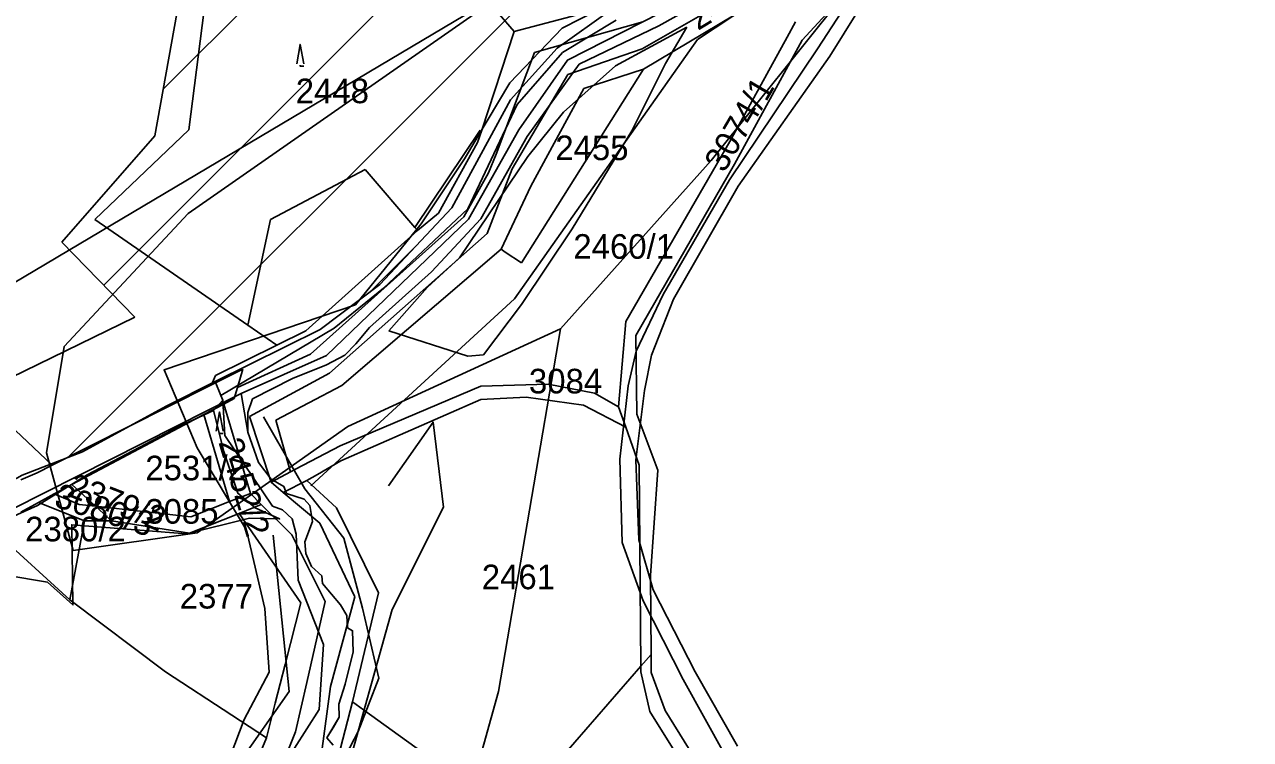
# Model space of a CAD drawing. Extents: x -564810 to -550519, y -1045831 to -1034011.
# Drawn here: x -551752.9 to -551498.8, y -1037775.2 to -1037627.1 of the extents above; entities that cross this region are included whole.
import ezdxf

# ---------------------------------------------------------------- set-up
doc = ezdxf.new("R2010")
doc.units = 0
for name, color, linetype in [('Interakční prvky', 7, 'Continuous'), ('KN stav', 7, 'Continuous'), ('Lesní porost', 7, 'Continuous'), ('Parcelní čísla', 7, 'Continuous'), ('Polní cesty stavající', 7, 'Continuous'), ('STG', 7, 'Continuous'), ('vodní toky', 7, 'Continuous'), ('Vrstva 18', 7, 'Continuous'), ('Vrstva 33', 7, 'Continuous'), ('Vrstva 4', 7, 'Continuous'), ('zamokř ploch', 7, 'Continuous')]:
    doc.layers.add(name, color=color, linetype=linetype)

msp = doc.modelspace()

# ---------------------------------------------------------------- linework, layer by layer
at = {"layer": 'Interakční prvky'}
msp.add_lwpolyline([(-551815.2, -1038103.87), (-551768.89, -1038062), (-551754.38, -1038041.34), (-551734.29, -1037993.33), (-551703.6, -1037883.91), (-551714.2, -1037828.76), (-551708.61, -1037780.35), (-551698.01, -1037765.28), (-551701.36, -1037732.9)], dxfattribs=at)
at = {"layer": 'KN stav'}
for p, q in [((-551667.33, -1037609.97), (-551651.38, -1037628.5)), ((-551624.88, -1037632.08), (-551586.71, -1037610.2)), ((-551574.97, -1037612.18), (-551591.71, -1037630.26)), ((-551718.79, -1037648.87), (-551714.95, -1037618.6)), ((-551651.38, -1037628.5), (-551628.05, -1037622.34)), ((-551602.54, -1037623.18), (-551624.56, -1037636.32)), ((-551624.72, -1037626.5), (-551647.19, -1037632.84)), ((-551594.84, -1037629.65), (-551593.1, -1037626.47)), ((-551651.38, -1037628.5), (-551658.1, -1037648.95)), ((-551606.67, -1037651.28), (-551594.84, -1037629.65)), ((-551591.71, -1037630.26), (-551605.76, -1037655.96)), ((-551647.19, -1037632.84), (-551655.15, -1037653.95)), ((-551640.25, -1037637.4), (-551624.88, -1037632.08)), ((-551624.56, -1037636.32), (-551649.88, -1037676.41)), ((-551636.95, -1037640.33), (-551624.56, -1037636.32)), ((-551651.83, -1037656.95), (-551640.25, -1037637.4)), ((-551647.92, -1037660.53), (-551636.95, -1037640.33)), ((-551738.32, -1037667.46), (-551718.79, -1037648.87)), ((-551658.1, -1037648.95), (-551658.97, -1037651.49)), ((-551658.97, -1037651.49), (-551667.1, -1037666.17)), ((-551628.22, -1037688.57), (-551606.67, -1037651.28)), ((-551655.15, -1037653.95), (-551656.73, -1037657.8)), ((-551656.99, -1037670.36), (-551651.83, -1037656.95)), ((-551605.76, -1037655.96), (-551626.14, -1037691.53)), ((-551656.73, -1037657.8), (-551661.85, -1037666.91)), ((-551654.09, -1037673.64), (-551647.92, -1037660.53)), ((-551706.6, -1037689.39), (-551738.32, -1037667.46)), ((-551661.85, -1037666.91), (-551693.62, -1037695.4)), ((-551667.1, -1037666.17), (-551671.45, -1037669.76)), ((-551671.45, -1037669.76), (-551694.55, -1037690.55)), ((-551689.67, -1037699.31), (-551656.99, -1037670.36)), ((-551654.09, -1037673.64), (-551687.08, -1037701.85)), ((-551653.24, -1037674.2), (-551654.09, -1037673.64)), ((-551649.88, -1037676.41), (-551653.24, -1037674.2)), ((-551700.6, -1037693.54), (-551706.6, -1037689.39)), ((-551629.77, -1037706.31), (-551628.22, -1037688.57)), ((-551694.55, -1037690.55), (-551700.6, -1037693.54)), ((-551626.14, -1037691.53), (-551626, -1037707.78)), ((-551713.26, -1037699.78), (-551700.6, -1037693.54)), ((-551693.62, -1037695.4), (-551708.72, -1037702.26)), ((-551768.83, -1037697.93), (-551747.1, -1037718.36)), ((-551707.63, -1037698.48), (-551714.09, -1037701.73)), ((-551714.09, -1037701.73), (-551713.26, -1037699.78)), ((-551708.72, -1037702.26), (-551707.63, -1037698.48)), ((-551706.26, -1037708.3), (-551689.67, -1037699.31)), ((-551714.09, -1037701.73), (-551723.13, -1037706.29)), ((-551708.72, -1037702.26), (-551709.39, -1037704.55)), ((-551687.08, -1037701.85), (-551700.76, -1037709.06)), ((-551658.32, -1037701.99), (-551687.43, -1037714.36)), ((-551644.32, -1037701.62), (-551658.32, -1037701.99)), ((-551634.72, -1037703.43), (-551644.32, -1037701.62)), ((-551715.71, -1037707.9), (-551711.57, -1037705.7)), ((-551709.39, -1037704.55), (-551711.57, -1037705.7)), ((-551711.57, -1037705.7), (-551706.06, -1037724.25)), ((-551658.3, -1037704.79), (-551687.32, -1037717.46)), ((-551648.87, -1037704.27), (-551658.3, -1037704.79)), ((-551636.99, -1037705.97), (-551648.87, -1037704.27)), ((-551629.77, -1037706.31), (-551634.72, -1037703.43)), ((-551723.13, -1037706.29), (-551747.1, -1037718.36)), ((-551722.09, -1037711.28), (-551715.71, -1037707.9)), ((-551715.71, -1037707.9), (-551710.35, -1037725.92)), ((-551628.28, -1037710.49), (-551636.99, -1037705.97)), ((-551628.28, -1037710.49), (-551629.77, -1037706.31)), ((-551626, -1037707.78), (-551621.64, -1037719.38)), ((-551701.75, -1037721.9), (-551706.26, -1037708.3)), ((-551700.76, -1037709.06), (-551697.74, -1037719.79)), ((-551625.46, -1037718.38), (-551628.28, -1037710.49)), ((-551743.06, -1037722.39), (-551722.09, -1037711.28)), ((-551687.43, -1037714.36), (-551696.7, -1037719.24)), ((-551747.1, -1037718.36), (-551750.23, -1037719.94)), ((-551687.32, -1037717.46), (-551692.16, -1037720.28)), ((-551625.17, -1037760.06), (-551625.46, -1037718.38)), ((-551750.23, -1037719.94), (-551753.63, -1037721.44)), ((-551697.74, -1037719.79), (-551701.75, -1037721.9)), ((-551697.74, -1037719.79), (-551696.7, -1037719.24)), ((-551692.16, -1037720.28), (-551694.37, -1037721.57)), ((-551621.64, -1037719.38), (-551623.16, -1037741.27)), ((-551746.69, -1037724.31), (-551743.06, -1037722.39)), ((-551743.06, -1037722.39), (-551738.16, -1037726.88)), ((-551699.28, -1037724.04), (-551701.75, -1037721.9)), ((-551694.37, -1037721.57), (-551699.28, -1037724.04)), ((-551694.37, -1037721.57), (-551688.23, -1037727.19)), ((-551749.94, -1037726.09), (-551746.69, -1037724.31)), ((-551746.69, -1037724.31), (-551741.52, -1037726.51)), ((-551710.35, -1037725.92), (-551718.4, -1037729.06)), ((-551706.06, -1037724.25), (-551710.35, -1037725.92)), ((-551706.06, -1037724.25), (-551703.8, -1037726.56)), ((-551691.63, -1037730.42), (-551699.28, -1037724.04)), ((-551753.62, -1037728.1), (-551749.94, -1037726.09)), ((-551749.94, -1037726.09), (-551740.44, -1037729.94)), ((-551741.52, -1037726.51), (-551738.16, -1037726.88)), ((-551738.16, -1037726.88), (-551734.84, -1037729.93)), ((-551718.4, -1037729.06), (-551738.16, -1037726.88)), ((-551708.41, -1037728.4), (-551718.69, -1037732.49)), ((-551703.8, -1037726.56), (-551708.41, -1037728.4)), ((-551708.41, -1037728.4), (-551695.58, -1037746.9)), ((-551703.8, -1037726.56), (-551697.49, -1037732.79)), ((-551688.23, -1037727.19), (-551679.48, -1037744.81)), ((-551740.44, -1037729.94), (-551743.48, -1037746.26)), ((-551734.84, -1037729.93), (-551740.44, -1037729.94)), ((-551718.69, -1037732.49), (-551734.84, -1037729.93)), ((-551684.39, -1037745.68), (-551691.63, -1037730.42)), ((-551743.48, -1037746.26), (-551759.69, -1037731.54)), ((-551697.49, -1037732.79), (-551690.58, -1037746.6)), ((-551623.16, -1037741.27), (-551623.02, -1037757.59)), ((-551743.48, -1037746.26), (-551723.63, -1037761.18)), ((-551689.42, -1037764.26), (-551684.39, -1037745.68)), ((-551679.48, -1037744.81), (-551684.89, -1037767.43)), ((-551695.58, -1037746.9), (-551698.85, -1037759.7)), ((-551690.58, -1037746.6), (-551694.37, -1037763.41)), ((-551623.02, -1037757.59), (-551625.17, -1037760.06)), ((-551623.02, -1037757.59), (-551622.99, -1037761.32)), ((-551723.63, -1037761.18), (-551709.88, -1037770.22)), ((-551698.85, -1037759.7), (-551700.89, -1037767.73)), ((-551625.17, -1037760.06), (-551652.1, -1037791.03)), ((-551625.17, -1037760.06), (-551625.16, -1037761.21)), ((-551625.16, -1037761.21), (-551623.28, -1037769.41)), ((-551622.99, -1037761.32), (-551620.07, -1037769.24)), ((-551694.37, -1037763.41), (-551696.68, -1037773.64)), ((-551691.33, -1037778.14), (-551689.42, -1037764.26)), ((-551700.89, -1037767.73), (-551702.73, -1037774.92)), ((-551684.89, -1037767.43), (-551689.26, -1037784.27)), ((-551682.63, -1037769.06), (-551684.89, -1037767.43)), ((-551652.1, -1037791.03), (-551682.63, -1037769.06)), ((-551620.07, -1037769.24), (-551615.23, -1037777.03)), ((-551709.88, -1037770.22), (-551702.73, -1037774.92)), ((-551623.28, -1037769.41), (-551618.22, -1037777.52)), ((-551696.68, -1037773.64), (-551698.38, -1037777.78)), ((-551702.73, -1037774.92), (-551713.64, -1037801.32))]:
    msp.add_line(p, q, dxfattribs=at)
at = {"layer": 'Lesní porost'}
for p, q in [((-551743.87, -1037716.79), (-551593.46, -1037566.38)), ((-551736.42, -1037681.06), (-551646.24, -1037590.87)), ((-551724.1, -1037640.45), (-551679.29, -1037595.65)), ((-551719.58, -1037615.34), (-551725.84, -1037650.11)), ((-551642.5, -1037631.93), (-551631.2, -1037623.93)), ((-551615.58, -1037627.59), (-551630.37, -1037635.62)), ((-551620, -1037635.14), (-551615.58, -1037627.59)), ((-551652.17, -1037642.66), (-551642.5, -1037631.93)), ((-551630.37, -1037635.62), (-551641.16, -1037645.25)), ((-551627, -1037649.06), (-551620, -1037635.14)), ((-551664.3, -1037665.02), (-551652.17, -1037642.66)), ((-551641.16, -1037645.25), (-551648.57, -1037654.38)), ((-551639.4, -1037669.39), (-551627, -1037649.06)), ((-551725.84, -1037650.11), (-551745.1, -1037672.13)), ((-551648.57, -1037654.38), (-551662.75, -1037675.41)), ((-551679.25, -1037680.94), (-551664.3, -1037665.02)), ((-551649.89, -1037685.11), (-551639.4, -1037669.39)), ((-551745.1, -1037672.13), (-551729.97, -1037687.69)), ((-551681.26, -1037682.46), (-551671.79, -1037672.99)), ((-551662.75, -1037675.41), (-551669.36, -1037681.48)), ((-551691.57, -1037690.29), (-551679.25, -1037680.94)), ((-551669.36, -1037681.48), (-551677.36, -1037690.56)), ((-551657.71, -1037695.52), (-551649.89, -1037685.11)), ((-551729.97, -1037687.69), (-551760.96, -1037702.81)), ((-551713.37, -1037701.07), (-551691.57, -1037690.29)), ((-551677.36, -1037690.56), (-551661, -1037695.76)), ((-551661, -1037695.76), (-551657.71, -1037695.52))]:
    msp.add_line(p, q, dxfattribs=at)
for points in [[(-551753.34, -1037720.45), (-551740.86, -1037715.63), (-551723.49, -1037706.18), (-551713.37, -1037701.07)], [(-551765.84, -1037739.68), (-551748.12, -1037742.61), (-551742.85, -1037747.34), (-551743.08, -1037730.72), (-551719.28, -1037732.6), (-551706.26, -1037729.39), (-551700, -1037729.51), (-551705.04, -1037727.2), (-551708.65, -1037724.18), (-551711.56, -1037715.54), (-551713.69, -1037707.08), (-551720.97, -1037710.45), (-551720.97, -1037710.45), (-551739.85, -1037720.4), (-551750.16, -1037726.73), (-551757.06, -1037729.83), (-551762.44, -1037731.84)]]:
    msp.add_lwpolyline(points, dxfattribs=at)
at = {"layer": 'Polní cesty stavající'}
for points in [[(-551607.6, -1037778.63), (-551616.38, -1037762.77), (-551624.67, -1037746.49), (-551629.01, -1037734.43), (-551629.48, -1037717.16), (-551627.77, -1037701.95), (-551626.13, -1037694.78), (-551620.5, -1037682.99), (-551606.77, -1037659.27), (-551588.5, -1037632.12), (-551579.51, -1037618.12)], [(-551577.04, -1037619.25), (-551585.95, -1037633.6), (-551604.95, -1037660.54), (-551618.36, -1037683.98), (-551622.94, -1037695.57), (-551624.41, -1037702.92), (-551626.14, -1037717.27), (-551625.57, -1037733.84), (-551622.56, -1037744.2), (-551613.87, -1037761.18), (-551605.09, -1037776.64)]]:
    msp.add_lwpolyline(points, dxfattribs=at)
at = {"layer": 'STG'}
for points in [[(-552085.98, -1037726.88), (-551997.79, -1037717.69), (-551885.73, -1037708.5), (-551777.34, -1037693.8), (-551650.58, -1037618.46), (-551597.31, -1037544.96), (-551593.63, -1037467.78), (-551597.31, -1037397.95), (-551586.28, -1037311.58), (-551545.87, -1037245.43), (-551516.47, -1037186.63), (-551459.52, -1037149.88), (-551378.69, -1037116.8), (-551273.98, -1037100.26), (-551202.33, -1037076.37), (-551108.64, -1037028.6), (-550987.39, -1036980.82), (-550890.39, -1036925.69), (-550831.6, -1036883.43), (-550758.12, -1036817.27), (-550710.36, -1036749.28), (-550693.82, -1036703.34), (-550693.82, -1036639.03), (-550758.12, -1036504.88)], [(-551513.17, -1037416.33), (-551527.86, -1037499.02), (-551537.05, -1037557.82), (-551573.79, -1037609.27), (-551610.53, -1037655.21), (-551641.76, -1037690.13), (-551685.86, -1037710.34), (-551717.09, -1037732.39), (-551742.81, -1037736.07), (-551748.32, -1037715.85), (-551744.64, -1037693.8), (-551718.92, -1037666.24), (-551650.58, -1037618.46)], [(-551627.07, -1038399.26), (-551669.32, -1038276.14), (-551682.18, -1038224.68), (-551704.23, -1038112.59), (-551720.76, -1038029.9), (-551711.57, -1037982.12), (-551685.86, -1037877.38), (-551654.62, -1037765.29), (-551641.76, -1037690.13)]]:
    msp.add_lwpolyline(points, dxfattribs=at)
at = {"layer": 'vodní toky'}
for p, q in [((-551621.41, -1037627.31), (-551591.57, -1037610.62)), ((-551630.28, -1037626.18), (-551641.37, -1037632.87)), ((-551637.94, -1037635.25), (-551621.41, -1037627.31)), ((-551641.37, -1037632.87), (-551650.79, -1037643.66)), ((-551648.66, -1037650.25), (-551637.94, -1037635.25)), ((-551650.79, -1037643.66), (-551661.02, -1037665.28)), ((-551658.32, -1037667.3), (-551648.66, -1037650.25)), ((-551661.02, -1037665.28), (-551678.47, -1037681.72)), ((-551668.53, -1037678.28), (-551658.32, -1037667.3)), ((-551681.38, -1037689.83), (-551668.53, -1037678.28)), ((-551678.47, -1037681.72), (-551688.66, -1037690)), ((-551688.66, -1037690), (-551712.17, -1037703.92)), ((-551684.17, -1037693.23), (-551681.38, -1037689.83)), ((-551686.47, -1037695.61), (-551684.17, -1037693.23)), ((-551697.33, -1037700.41), (-551690.28, -1037697.6)), ((-551690.28, -1037697.6), (-551686.47, -1037695.61)), ((-551705.64, -1037704.6), (-551697.33, -1037700.41)), ((-551712.17, -1037703.92), (-551711.78, -1037704.93)), ((-551711.78, -1037704.93), (-551711.34, -1037712.26)), ((-551706.59, -1037707.47), (-551705.64, -1037704.6)), ((-551706.55, -1037711.51), (-551706.59, -1037707.47)), ((-551711.34, -1037712.26), (-551701.47, -1037726.9)), ((-551704.4, -1037717.84), (-551706.55, -1037711.51)), ((-551701.78, -1037721.28), (-551704.4, -1037717.84)), ((-551699.1, -1037722.79), (-551701.78, -1037721.28)), ((-551698.56, -1037724.22), (-551699.1, -1037722.79)), ((-551694.93, -1037725.43), (-551698.56, -1037724.22)), ((-551693.71, -1037726.76), (-551694.93, -1037725.43)), ((-551701.47, -1037726.9), (-551699.42, -1037727.64)), ((-551699.42, -1037727.64), (-551697.39, -1037729.5)), ((-551693.16, -1037730.08), (-551693.71, -1037726.76)), ((-551697.39, -1037729.5), (-551696.57, -1037732.69)), ((-551694.76, -1037734.25), (-551693.16, -1037730.08)), ((-551696.57, -1037732.69), (-551696.14, -1037742.22)), ((-551694.55, -1037736.69), (-551694.76, -1037734.25)), ((-551693.37, -1037739.39), (-551694.55, -1037736.69)), ((-551691.26, -1037741.29), (-551693.37, -1037739.39)), ((-551691.1, -1037742.87), (-551691.26, -1037741.29)), ((-551696.14, -1037742.22), (-551690.91, -1037755.55)), ((-551687.37, -1037747.31), (-551691.1, -1037742.87)), ((-551686.09, -1037749.52), (-551687.37, -1037747.31)), ((-551685.96, -1037752.06), (-551686.09, -1037749.52)), ((-551684.89, -1037752.69), (-551685.96, -1037752.06)), ((-551684.72, -1037757.04), (-551684.89, -1037752.69)), ((-551690.91, -1037755.55), (-551691.8, -1037769)), ((-551686.38, -1037763.74), (-551684.72, -1037757.04)), ((-551687.71, -1037767.9), (-551686.38, -1037763.74)), ((-551691.8, -1037769), (-551701.04, -1037783.42)), ((-551687.63, -1037770.58), (-551687.71, -1037767.9)), ((-551688.86, -1037772.68), (-551687.63, -1037770.58)), ((-551690.23, -1037774.92), (-551688.86, -1037772.68)), ((-551688.91, -1037776.38), (-551690.23, -1037774.92))]:
    msp.add_line(p, q, dxfattribs=at)
msp.add_lwpolyline([(-551841.01, -1037775.91), (-551797.34, -1037751.57), (-551772.81, -1037738.22), (-551762.55, -1037731.81), (-551757.06, -1037729.83), (-551750.16, -1037726.73), (-551739.85, -1037720.4), (-551720.97, -1037710.45), (-551713.69, -1037707.08), (-551711.78, -1037704.93), (-551712.17, -1037703.92), (-551713.37, -1037701.07), (-551723.49, -1037706.18), (-551740.86, -1037715.63), (-551753.34, -1037720.45), (-551759.89, -1037724.09), (-551767.01, -1037728.36), (-551802.6, -1037747.89), (-551819.78, -1037756.67), (-551841.14, -1037768.44), (-551881.5, -1037790.23)], dxfattribs=at)
at = {"layer": 'Vrstva 18'}
for points in [[(-551544.76, -1037370.3), (-551552.65, -1037393.75), (-551550.94, -1037437.24), (-551554.78, -1037458.77), (-551534.74, -1037459.2), (-551525.57, -1037497.78), (-551513.85, -1037519.32), (-551505.75, -1037542.98), (-551507.66, -1037555.13), (-551531.75, -1037621), (-551553.07, -1037607.79), (-551573.11, -1037603.52), (-551613.4, -1037630.17), (-551651.35, -1037683.89), (-551693.56, -1037722.69)], [(-551717.11, -1037714.8), (-551723.94, -1037698.6), (-551684.28, -1037685.17), (-551670.64, -1037668.33), (-551661.69, -1037654.9), (-551652.31, -1037639.12), (-551641.43, -1037627.82), (-551618.62, -1037616.1), (-551603.7, -1037608.42), (-551592.4, -1037601.18), (-551580.68, -1037591.8), (-551571.94, -1037579.65), (-551568.1, -1037567.92), (-551562.35, -1037555.34), (-551561.28, -1037542.13), (-551560.21, -1037528.06), (-551577.48, -1037494.37), (-551581.53, -1037485.42), (-551581.74, -1037476.47), (-551577.27, -1037465.17), (-551571.94, -1037450.67), (-551567.89, -1037437.88)], [(-551703.32, -1037708.36), (-551694.79, -1037723.28), (-551686.69, -1037733.51), (-551682.85, -1037748.01), (-551679.44, -1037762.51), (-551683.71, -1037773.59), (-551693.94, -1037793.2), (-551702.04, -1037811.96), (-551697.35, -1037830.3), (-551691.38, -1037846.5), (-551689.25, -1037856.31), (-551682.43, -1037865.69), (-551670.06, -1037881.89), (-551673.9, -1037888.28), (-551687.54, -1037902.35), (-551693.51, -1037916.42), (-551702.04, -1037944.14), (-551708.43, -1037968.44), (-551717.39, -1038001.69), (-551724.21, -1038015.76)], [(-551771.69, -1038052.9), (-551752.5, -1038020.71), (-551741.63, -1037995.99), (-551732.46, -1037959.74), (-551722.02, -1037918.39), (-551716.05, -1037888.12), (-551714.56, -1037861.9), (-551720.1, -1037833.33), (-551719.46, -1037818.19), (-551716.47, -1037795.17), (-551707.31, -1037771.08), (-551702.19, -1037761.27), (-551703.04, -1037748.06), (-551706.88, -1037731.86), (-551717.11, -1037714.8)]]:
    msp.add_lwpolyline(points, dxfattribs=at)
at = {"layer": 'Vrstva 33'}
for points in [[(-551707.95, -1037703.51), (-551690.27, -1037695.68), (-551660.88, -1037667.42), (-551650.45, -1037648.86), (-551640.35, -1037634.41), (-551609.63, -1037618.75), (-551585.86, -1037603.82), (-551565.69, -1037581.65), (-551557.72, -1037554.32), (-551555.13, -1037528.84), (-551555.55, -1037521.97), (-551574.89, -1037484.48), (-551574.02, -1037470.75), (-551566.42, -1037460.75), (-551561.55, -1037439.24)], [(-551707.95, -1037703.51), (-551796.1, -1037748.03), (-551841.58, -1037772.91), (-551912.77, -1037811.01), (-551947.88, -1037830.27), (-551968.23, -1037855.25), (-551986.23, -1037865.71), (-552006.06, -1037866.84)], [(-551688.91, -1037776.38), (-551690.23, -1037774.92), (-551687.63, -1037770.58), (-551687.71, -1037767.9), (-551686.38, -1037763.74), (-551684.72, -1037757.04), (-551684.89, -1037752.69), (-551685.96, -1037752.06), (-551686.09, -1037749.52), (-551687.37, -1037747.31), (-551691.1, -1037742.87), (-551691.26, -1037741.29), (-551693.37, -1037739.39), (-551694.55, -1037736.69), (-551694.76, -1037734.25), (-551693.16, -1037730.08), (-551693.71, -1037726.76), (-551694.93, -1037725.43), (-551698.56, -1037724.22), (-551699.1, -1037722.79), (-551701.78, -1037721.28), (-551704.4, -1037717.84), (-551706.55, -1037711.51), (-551707.95, -1037703.51)], [(-551730.02, -1038007.12), (-551721.85, -1037990.65), (-551695.72, -1037918.58), (-551685.13, -1037898.8), (-551672.41, -1037850.76), (-551677.36, -1037807.66), (-551686.54, -1037783.63), (-551676.65, -1037748.31), (-551666.06, -1037727.11), (-551668.18, -1037709.45), (-551677.44, -1037722.66)]]:
    msp.add_lwpolyline(points, dxfattribs=at)
at = {"layer": 'Vrstva 4'}
for p, q in [((-551658.43, -1037648.97), (-551671.97, -1037669.15)), ((-551701.89, -1037667.49), (-551682.25, -1037657.12)), ((-551682.25, -1037657.12), (-551671.97, -1037669.15)), ((-551706.6, -1037689.39), (-551701.89, -1037667.49)), ((-551671.97, -1037669.15), (-551671.45, -1037669.75))]:
    msp.add_line(p, q, dxfattribs=at)
at = {"layer": 'zamokř ploch'}
for points in [[(-551696.46, -1037635.18), (-551695.76, -1037631.18), (-551694.96, -1037635.18)], [(-551695.76, -1037635.48), (-551695.76, -1037635.68), (-551694.96, -1037635.68)], [(-551713.18, -1037711.34), (-551712.48, -1037707.34), (-551711.68, -1037711.34)], [(-551712.48, -1037711.64), (-551712.48, -1037711.84), (-551711.68, -1037711.84)]]:
    msp.add_lwpolyline(points, dxfattribs=at)

# ---------------------------------------------------------------- texts
at = {"layer": 'Parcelní čísla'}
for s, rotation, p in [('2460/2', 31.3014, (-551613.32, -1037628.4)), ('3074/1', 59.5037, (-551607.86, -1037657.97)), ('2452/2', 286.6533, (-551712.72, -1037713.59)), ('2379/2', 338.6991, (-551744.3, -1037724.63)), ('3080/3', 342.1399, (-551746.98, -1037726.87))]:
    msp.add_text(s, height=5.1, rotation=rotation, dxfattribs=at).set_placement(p)
for s, p in [('2448', (-551696.65, -1037643.36)), ('2455', (-551642.86, -1037655.16)), ('2460/1', (-551639.12, -1037675.6)), ('3084', (-551648.33, -1037703.51)), ('2531/2', (-551727.83, -1037721.52)), ('3085', (-551727.83, -1037730.5)), ('2380/2', (-551752.73, -1037734.17)), ('2461', (-551658.1, -1037744.09)), ('2377', (-551720.69, -1037748.09))]:
    msp.add_text(s, height=5.1, dxfattribs=at).set_placement(p)

doc.saveas('drawing.dxf')
